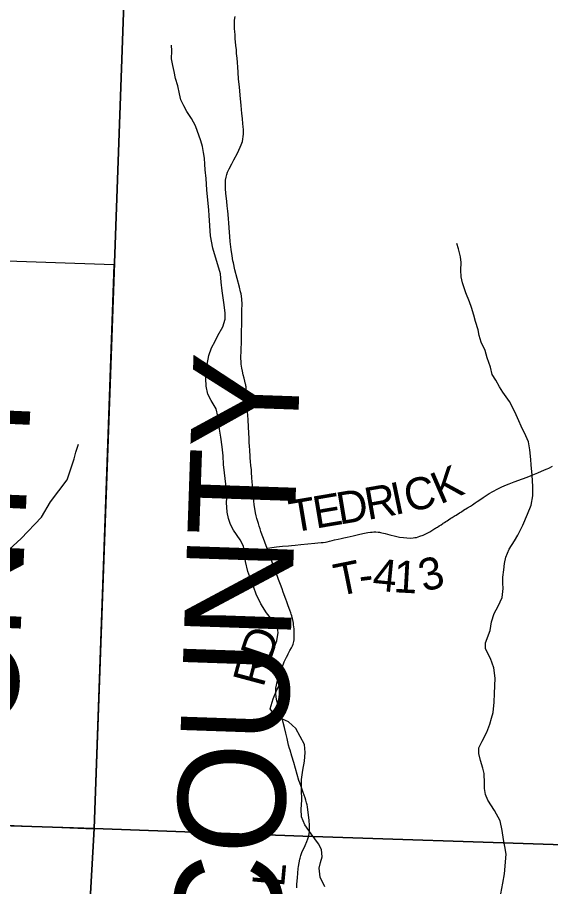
# Model space of a CAD drawing. Extents: x 0 to 34, y 0 to 22.
# Drawn here: x 28.529 to 29.474, y 18.142 to 19.68 of the extents above; entities that cross this region are included whole.
import ezdxf

# ---------------------------------------------------------------- set-up
doc = ezdxf.new("R2010")
doc.units = 0
for name, color, linetype in [('GM_X_Adjacent_County', 7, 'Continuous'), ('GM_X_Adjacent_County_Text', 7, 'Continuous'), ('GM_X_County', 7, 'Continuous'), ('GM_X_Minor_River', 7, 'Continuous'), ('GM_X_Section', 7, 'Continuous'), ('GM_X_Township', 7, 'Continuous'), ('GM_X_Township_Road', 7, 'Continuous'), ('GM_X_Township_Road_Text', 7, 'Continuous')]:
    doc.layers.add(name, color=color, linetype=linetype)

msp = doc.modelspace()

# ---------------------------------------------------------------- linework, layer by layer
at = {"layer": 'GM_X_Adjacent_County'}
for points in [[(28.7526, 20.9), (28.7366, 20.4185), (28.7263, 19.9342), (28.6656, 18.2443), (28.6433, 17.8576), (28.637, 17.506), (28.6368, 17.4981), (28.5999, 16.6109), (28.5991, 16.5887), (28.5955, 16.4142)], [(28.5955, 16.4142), (28.5991, 16.5887), (28.5999, 16.6109), (28.6368, 17.4981), (28.637, 17.506), (28.6433, 17.8576), (28.6656, 18.2443), (28.7263, 19.9342), (28.7366, 20.4185), (28.7526, 20.9)]]:
    msp.add_lwpolyline(points, dxfattribs=at)
at = {"layer": 'GM_X_County'}
for points in [[(28.5955, 16.4142), (28.5991, 16.5887), (28.5999, 16.6109), (28.6368, 17.4981), (28.637, 17.506), (28.6433, 17.8576), (28.6656, 18.2443), (28.7263, 19.9342), (28.7366, 20.4185), (28.7526, 20.9)], [(28.7526, 20.9), (28.7366, 20.4185), (28.7263, 19.9342), (28.6656, 18.2443), (28.6433, 17.8576), (28.637, 17.506), (28.6368, 17.4981), (28.5999, 16.6109), (28.5991, 16.5887), (28.5955, 16.4142)]]:
    msp.add_lwpolyline(points, dxfattribs=at)
at = {"layer": 'GM_X_Minor_River'}
for points in [[(28.869, 19.3289), (28.8685, 19.3388), (28.8652, 19.3744), (28.8635, 19.3948), (28.8622, 19.4096), (28.8613, 19.4202), (28.8605, 19.4304), (28.8589, 19.4403), (28.8573, 19.4512), (28.8545, 19.4614), (28.8448, 19.4875), (28.8375, 19.5007), (28.8295, 19.5131), (28.8241, 19.5229), (28.8187, 19.5335), (28.8163, 19.5441), (28.8135, 19.5588), (28.8096, 19.5717), (28.8072, 19.5838), (28.8049, 19.5944), (28.8025, 19.6061), (28.8027, 19.6205), (28.8026, 19.6303)], [(29.0737, 18.1413), (29.0656, 18.1583), (29.064, 18.1742), (29.0661, 18.1841), (29.0691, 18.1943), (29.0682, 18.2072), (29.0628, 18.2174), (29.0498, 18.2347), (29.0387, 18.2509), (29.0328, 18.2652), (29.032, 18.2788), (29.033, 18.2948), (29.0324, 18.3137), (29.0326, 18.3312), (29.0351, 18.3475), (29.038, 18.3634), (29.039, 18.3786), (29.0377, 18.393), (29.0223, 18.4213), (29.0094, 18.4329), (28.9991, 18.4381), (28.9854, 18.4448), (28.9773, 18.4561), (28.9821, 18.4739), (28.9891, 18.4895), (28.9958, 18.5017), (29.0014, 18.512), (28.9918, 18.5271), (28.9812, 18.5334), (28.9746, 18.5447), (28.9768, 18.5546), (28.9839, 18.5645), (28.9891, 18.5767), (28.9912, 18.5911), (28.9892, 18.6017), (28.9823, 18.6115), (28.9705, 18.6262), (28.9605, 18.642), (28.952, 18.6589), (28.9481, 18.671), (28.9408, 18.6895), (28.9373, 18.6994), (28.9333, 18.7171), (28.93, 18.744), (28.9242, 18.7553), (28.912, 18.7722), (28.907, 18.7821), (28.9031, 18.793), (28.9011, 18.804), (28.8998, 18.821), (28.9008, 18.8366), (28.8987, 18.8536), (28.8959, 18.874), (28.8946, 18.8884), (28.8937, 18.9036), (28.8921, 18.9199), (28.8896, 18.9369), (28.8876, 18.9509), (28.886, 18.9615), (28.8844, 18.974), (28.8812, 18.9868), (28.8724, 19.0019), (28.8666, 19.0128), (28.8638, 19.0272), (28.863, 19.0408), (28.8636, 19.056), (28.8683, 19.0815), (28.8731, 19.0948), (28.8794, 19.107), (28.8846, 19.1169), (28.8931, 19.1321), (28.8976, 19.1454), (28.8971, 19.1571), (28.895, 19.1753), (28.8922, 19.1958), (28.8905, 19.2113), (28.8893, 19.2257), (28.8842, 19.2415), (28.8787, 19.2612), (28.8756, 19.2714), (28.8716, 19.2933), (28.869, 19.3289)], [(29.3857, 18.1288), (29.3889, 18.1474), (29.3918, 18.1641), (29.3949, 18.199), (29.3925, 18.2126), (29.3901, 18.2247), (29.3877, 18.241), (29.3841, 18.258), (29.3745, 18.2761), (29.3626, 18.2946), (29.3583, 18.3048), (29.3563, 18.315), (29.3563, 18.3245), (29.3557, 18.3415), (29.3537, 18.3513), (29.3495, 18.3649), (29.3463, 18.377), (29.3466, 18.3873), (29.3525, 18.3987), (29.3607, 18.4151), (29.3659, 18.4292), (29.3688, 18.4398), (29.3718, 18.4497), (29.3739, 18.4679), (29.3745, 18.4834), (29.3757, 18.5107), (29.3733, 18.5289), (29.3671, 18.5455), (29.3586, 18.5625), (29.3581, 18.5731), (29.3663, 18.5948), (29.3691, 18.6103), (29.3735, 18.6248), (29.381, 18.6381), (29.388, 18.653), (29.3894, 18.6693), (29.3889, 18.6788), (29.3892, 18.689), (29.391, 18.7019), (29.392, 18.7136), (29.3946, 18.7247), (29.4005, 18.7384), (29.4094, 18.7532), (29.4158, 18.7635), (29.4243, 18.7814), (29.4325, 18.8005), (29.4391, 18.8168), (29.442, 18.8328), (29.4422, 18.8498), (29.4409, 18.8699), (29.4392, 18.8877), (29.4388, 18.8972), (29.4371, 18.9142), (29.4347, 18.9286), (29.4297, 18.9395), (29.4216, 18.9561), (29.4173, 18.9659), (29.4104, 18.9814), (29.4007, 19.0002), (29.3892, 19.0164), (29.3831, 19.0262), (29.3769, 19.0375), (29.3704, 19.0477), (29.3669, 19.0606), (29.361, 19.0772), (29.3579, 19.09), (29.3509, 19.1051), (29.3474, 19.1165), (29.3454, 19.1267), (29.3408, 19.1418), (29.3376, 19.1527), (29.3334, 19.166), (29.3299, 19.1762), (29.3233, 19.192), (29.3178, 19.2098), (29.3151, 19.2204), (29.3146, 19.2325), (29.3152, 19.2461), (29.314, 19.256), (29.3104, 19.27), (29.3073, 19.2798)], [(28.2814, 18.3155), (28.2838, 18.3207), (28.3576, 18.3894), (28.4018, 18.5006), (28.4258, 18.5584), (28.4345, 18.593), (28.4445, 18.6144), (28.4557, 18.6293), (28.463, 18.6506), (28.4686, 18.695), (28.4862, 18.7123), (28.5364, 18.7575), (28.5723, 18.7951), (28.5883, 18.8222), (28.6174, 18.8615), (28.6302, 18.8984), (28.6331, 18.9106), (28.6375, 18.9247)]]:
    msp.add_lwpolyline(points, dxfattribs=at)
at = {"layer": 'GM_X_Section'}
msp.add_lwpolyline([(28.7005, 19.2422), (28.6651, 18.2435), (27.6773, 18.2845), (27.7021, 19.2764)], close=True, dxfattribs=at)
at = {"layer": 'GM_X_Township'}
for points in [[(28.7526, 20.9), (28.7366, 20.4185), (28.7263, 19.9342), (28.6656, 18.2443), (29.0347, 18.2309), (29.9568, 18.1999), (30.8167, 18.1651)], [(26.6434, 18.3221), (26.6499, 18.322), (26.6542, 18.3216), (26.6574, 18.3212), (26.6605, 18.3207), (26.6635, 18.3199), (26.939, 18.3094), (27.3097, 18.2983), (27.6027, 18.2802), (27.8508, 18.2724), (28.0352, 18.266), (28.1353, 18.2617), (28.26, 18.2574), (28.6656, 18.2443), (28.7263, 19.9342)], [(28.5955, 16.4142), (28.5991, 16.5887), (28.5999, 16.6109), (28.6368, 17.4981), (28.637, 17.506), (28.6433, 17.8576), (28.6656, 18.2443), (28.26, 18.2574), (28.1353, 18.2617), (28.0352, 18.266), (27.8508, 18.2724), (27.6027, 18.2802), (27.3097, 18.2983), (26.939, 18.3094), (26.6635, 18.3199), (26.6605, 18.3207), (26.6574, 18.3212), (26.6542, 18.3216), (26.6499, 18.322), (26.6434, 18.3221)], [(30.8167, 18.1651), (29.9568, 18.1999), (29.0347, 18.2309), (28.6656, 18.2443), (28.6433, 17.8576), (28.637, 17.506), (28.6368, 17.4981), (28.5999, 16.6109), (28.5991, 16.5887), (28.5955, 16.4142)]]:
    msp.add_lwpolyline(points, dxfattribs=at)
at = {"layer": 'GM_X_Township_Road'}
for points in [[(28.9716, 18.7399), (28.9675, 18.7513), (28.9652, 18.7577), (28.963, 18.7635), (28.9608, 18.77), (28.9592, 18.7747), (28.9576, 18.7794), (28.9561, 18.7839), (28.9545, 18.7894), (28.9535, 18.793), (28.9523, 18.7977), (28.9512, 18.803), (28.9498, 18.8105), (28.9488, 18.8171), (28.948, 18.8241), (28.9473, 18.8309), (28.9469, 18.8383), (28.9464, 18.8426), (28.9459, 18.8513), (28.9452, 18.8587), (28.9448, 18.8641), (28.9448, 18.866), (28.9446, 18.8672), (28.9441, 18.8726), (28.9437, 18.8793), (28.9431, 18.8865), (28.9423, 18.8936), (28.9418, 18.9), (28.9416, 18.9037), (28.9414, 18.9074), (28.9412, 18.9086), (28.9408, 18.9141), (28.9404, 18.9209), (28.9399, 18.9277), (28.9396, 18.9344), (28.9388, 18.9543), (28.9379, 18.968), (28.9369, 18.9821), (28.9364, 18.9912), (28.9359, 19.002), (28.9354, 19.0115), (28.9353, 19.0149), (28.9351, 19.0171), (28.9346, 19.0219), (28.9343, 19.0262), (28.9341, 19.0275), (28.9338, 19.0294), (28.9335, 19.0307), (28.9322, 19.0359), (28.9309, 19.041), (28.9294, 19.0474), (28.9278, 19.0535), (28.9266, 19.059), (28.9262, 19.0625), (28.9257, 19.0661), (28.9255, 19.0703), (28.9254, 19.0769), (28.9254, 19.0813), (28.9255, 19.0859), (28.9258, 19.0941), (28.926, 19.1025), (28.9263, 19.1127), (28.9264, 19.1178), (28.9264, 19.1246), (28.9267, 19.1365), (28.927, 19.1516), (28.9271, 19.1615), (28.9273, 19.1723), (28.9268, 19.181), (28.9262, 19.1861), (28.9256, 19.1902), (28.9248, 19.1943), (28.9229, 19.202), (28.9146, 19.2332), (28.9119, 19.2451), (28.9111, 19.249), (28.9096, 19.258), (28.9079, 19.2687), (28.9064, 19.2832), (28.9051, 19.2999), (28.9045, 19.3067), (28.9038, 19.3166), (28.9032, 19.3228), (28.9025, 19.3315), (28.902, 19.337), (28.901, 19.346), (28.9002, 19.3536), (28.8987, 19.3687), (28.8982, 19.3764), (28.8978, 19.3832), (28.8978, 19.3873), (28.8981, 19.3918), (28.8989, 19.3971), (28.9003, 19.4019), (28.9017, 19.4057), (28.9045, 19.4115), (28.9093, 19.4206), (28.9128, 19.4273), (28.919, 19.4393), (28.9241, 19.4499), (28.9258, 19.4539), (28.9279, 19.4603), (28.9288, 19.4639), (28.9295, 19.4691), (28.9298, 19.4729), (28.9299, 19.4784), (28.9299, 19.4807), (28.9295, 19.4865), (28.9289, 19.4913), (28.928, 19.5007), (28.927, 19.5093), (28.9256, 19.5235), (28.9238, 19.542), (28.9225, 19.5567), (28.9212, 19.5702), (28.9202, 19.5826), (28.9197, 19.5915), (28.9191, 19.6001), (28.9185, 19.6075), (28.9177, 19.6156), (28.9172, 19.6221), (28.9164, 19.6298), (28.9158, 19.6365), (28.9153, 19.6414), (28.9149, 19.6487), (28.9144, 19.6544), (28.914, 19.6593), (28.9139, 19.6636), (28.9137, 19.6704), (28.9138, 19.6741), (28.9143, 19.6785), (28.9151, 19.6814)], [(28.9716, 18.7399), (28.9732, 18.7402), (28.9799, 18.7415), (28.9842, 18.7421), (28.9883, 18.7427), (28.9934, 18.7433), (28.9991, 18.7437), (29.0095, 18.7447), (29.0151, 18.7451), (29.0212, 18.7456), (29.0313, 18.7467), (29.0438, 18.7479), (29.0559, 18.7491), (29.0613, 18.7496), (29.0674, 18.7502), (29.0706, 18.7506), (29.0753, 18.7513), (29.0779, 18.7518), (29.0824, 18.7527), (29.0869, 18.7539), (29.0912, 18.755), (29.0977, 18.7565), (29.1026, 18.7575), (29.1077, 18.7587), (29.1132, 18.76), (29.1242, 18.7624), (29.1332, 18.7644), (29.1411, 18.7662), (29.1469, 18.7675), (29.1501, 18.7681), (29.1545, 18.7686), (29.1576, 18.7689), (29.1606, 18.7691), (29.1642, 18.7691), (29.1681, 18.7687), (29.1704, 18.7685), (29.1726, 18.7682), (29.175, 18.7677), (29.1806, 18.7663), (29.189, 18.7641), (29.1991, 18.7614), (29.2014, 18.7609), (29.2059, 18.7601), (29.2134, 18.7591), (29.2191, 18.7585), (29.2258, 18.7584), (29.2305, 18.7588), (29.233, 18.7591), (29.2361, 18.7596), (29.239, 18.7604), (29.2423, 18.7614), (29.2478, 18.7635), (29.2528, 18.7659), (29.256, 18.7675), (29.2595, 18.7695), (29.2631, 18.7716), (29.2651, 18.7729), (29.2666, 18.7738), (29.2687, 18.7751), (29.2697, 18.7756), (29.2717, 18.7769), (29.2732, 18.7778), (29.2762, 18.7798), (29.2772, 18.7804), (29.2797, 18.7819), (29.2826, 18.7839), (29.2835, 18.7846), (29.286, 18.7861), (29.288, 18.7874), (29.2905, 18.7891), (29.293, 18.7907), (29.2971, 18.7933), (29.2991, 18.7946), (29.3012, 18.7959), (29.3048, 18.7982), (29.3064, 18.7991), (29.3121, 18.8027), (29.3157, 18.805), (29.3196, 18.8074), (29.3264, 18.8116), (29.3316, 18.8149), (29.3353, 18.8173), (29.3401, 18.8206), (29.3436, 18.8228), (29.35, 18.8272), (29.3541, 18.83), (29.3649, 18.837), (29.3714, 18.8409), (29.3801, 18.8457), (29.3863, 18.8486), (29.3925, 18.8513), (29.4, 18.8542), (29.4093, 18.8576), (29.4238, 18.8629), (29.4319, 18.8659), (29.4422, 18.8701), (29.4509, 18.8736), (29.4628, 18.8788), (29.4674, 18.8808), (29.4702, 18.8821), (29.4769, 18.8854)], [(28.9791, 18.7193), (28.9767, 18.726), (28.9744, 18.7325), (28.9716, 18.7399)], [(29.0452, 18.2305), (29.0454, 18.2315), (29.0458, 18.2333), (29.0459, 18.2346), (29.0465, 18.2399), (29.0467, 18.244), (29.0468, 18.2465), (29.0467, 18.2505), (29.046, 18.2584), (29.0448, 18.2688), (29.0439, 18.2772), (29.043, 18.283), (29.0423, 18.2865), (29.0416, 18.2896), (29.0403, 18.2943), (29.039, 18.2984), (29.0375, 18.3032), (29.0357, 18.3084), (29.0319, 18.3189), (29.0294, 18.325), (29.0279, 18.3293), (29.0248, 18.3399), (29.0218, 18.3506), (29.0189, 18.3609), (29.0155, 18.3726), (29.0123, 18.3828), (29.0114, 18.386), (29.0098, 18.392), (29.007, 18.4036), (29.0048, 18.4128), (29.0024, 18.423), (29.0001, 18.4321), (28.9981, 18.4399), (28.9957, 18.4477), (28.9922, 18.4598), (28.9904, 18.4649), (28.9894, 18.4687), (28.9884, 18.4728), (28.9877, 18.4777), (28.987, 18.4827), (28.9869, 18.4866), (28.9873, 18.4925), (28.9883, 18.4978), (28.9896, 18.5037), (28.9906, 18.5074), (28.9916, 18.511), (28.9927, 18.5147), (28.994, 18.5187), (28.9955, 18.5233), (28.9966, 18.5266), (28.9993, 18.5328), (29.0006, 18.5357), (29.0021, 18.5392), (29.0031, 18.5414), (29.0047, 18.5451), (29.006, 18.5477), (29.0081, 18.5517), (29.0089, 18.5533), (29.0121, 18.5593), (29.0148, 18.5639), (29.0161, 18.5664), (29.0168, 18.5679), (29.0176, 18.5705), (29.0189, 18.5752), (29.0194, 18.578), (29.0196, 18.5817), (29.0197, 18.5838), (29.0198, 18.5861), (29.0198, 18.5877), (29.0195, 18.5922), (29.0193, 18.5976), (29.0185, 18.6046), (29.0181, 18.6076), (29.0177, 18.6104), (29.0165, 18.6162), (29.016, 18.618), (29.0154, 18.6205), (29.0144, 18.6239), (29.0136, 18.626), (29.0119, 18.6305), (29.0089, 18.6387), (29.0065, 18.6456), (29.0047, 18.6503), (29.0002, 18.6627), (28.9982, 18.6684), (28.9954, 18.6759), (28.992, 18.6848), (28.9899, 18.6901), (28.9855, 18.7019), (28.9792, 18.7192), (28.9791, 18.7193)], [(29.024, 18.1396), (29.0245, 18.146), (29.0252, 18.157), (29.0259, 18.1652), (29.0268, 18.1737), (29.0272, 18.1769), (29.0284, 18.1835), (29.0296, 18.1899), (29.0301, 18.192), (29.0307, 18.1945), (29.0314, 18.1968), (29.0332, 18.2017), (29.0388, 18.2143), (29.0417, 18.2212), (29.0438, 18.2264), (29.0448, 18.2294), (29.0452, 18.2305)]]:
    msp.add_lwpolyline(points, dxfattribs=at)

# ---------------------------------------------------------------- texts
at = {"layer": 'GM_X_Adjacent_County_Text'}
for s, height, rotation, p in [('GUERNSEY COUNTY', 0.189394, 88.0332, (28.9429, 16.5222)), ('Y', 0.1894, 87.496, (28.548, 18.8862)), ('T', 0.1894, 87.496, (28.5418, 18.7447)), ('N', 0.1894, 87.496, (28.5345, 18.5774)), ('U', 0.1894, 87.496, (28.5271, 18.41))]:
    msp.add_text(s, height=height, rotation=rotation, dxfattribs=at).set_placement(p)
at = {"layer": 'GM_X_Township_Road_Text'}
for s, rotation, p in [('K', 23.5251, (29.278, 18.8173)), ('I', 11.794, (29.1974, 18.7989)), ('C', 12.1609, (29.2207, 18.8037)), ('D', 9.4408, (29.0996, 18.782)), ('R', 10.0899, (29.1497, 18.7903)), ('T', 9.5581, (29.0159, 18.7679)), ('E', 9.5539, (29.0578, 18.775)), ('T', 11.5024, (29.0965, 18.6552)), ('4', 354.2242, (29.1568, 18.6663)), ('3', 14.9917, (29.2488, 18.6627)), ('1', 356.8543, (29.1945, 18.6626)), ('-', 7.0747, (29.137, 18.6635)), ('D', 71.2609, (28.9769, 18.537)), ('R', 74.9821, (28.9651, 18.4928)), ('L', 84.7039, (29.0016, 18.1394))]:
    msp.add_text(s, height=0.0568, rotation=rotation, dxfattribs=at).set_placement(p)

doc.saveas('drawing.dxf')
